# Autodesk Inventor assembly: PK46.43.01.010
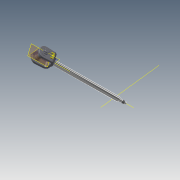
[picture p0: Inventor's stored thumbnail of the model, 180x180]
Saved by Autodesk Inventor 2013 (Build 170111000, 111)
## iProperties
Shininess: 64.0
Length Units: 11269
Angle Units: 11279
Time Units: 11290
Mass Units: 11283
Length Display Precision: 3
Angle Display Precision: 2
Compacted: True
Created: 2004-11
Part Number: PK46.43.01.010
Document SubType Name: Assembly
Designer: ELarisa
Manufacturer: Standard
Standards Organization: Custom
Mass: 71216.7 g
Surface Area: 7364.67 cm^2
Volume: 9076.79 cm^3
Density: 7.84603 g/cm^3
Density: 0.0
Volumn: 0.0
Area: 0.0
PropertySet Name: Model Information
Control State: 0
Master: False
Checked Out: False
Checked Out Date: 2008-10-09
Last Check In Date: 2008-10-09
Author: ELarisa
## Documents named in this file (8)
- D:\FrontLoaderVault\Data\Assy, Chassis, Front\PK46.43.01.010.iam
- D:\FrontLoaderVault\Data\Assy, Chassis, Front\PK46.43.01.001.ipt
- D:\FrontLoaderVault\Data\Assy, Chassis, Front\PK46.43.01.008.ipt
- D:\FrontLoaderVault\Data\Assy, Chassis, Front\PK30.25.00.005.ipt
- D:\FrontLoaderVault\Data\Assy, Chassis, Front\PK46.25.00.007.ipt
- D:\FrontLoaderVault\Data\Assy, Chassis, Front\PK46.25.00.010.iam
- D:\FrontLoaderVault\Data\Assy, Chassis, Front\PK46.25.00.005.ipt
- D:\FrontLoaderVault\Data\Assy, Chassis, Front\PK46.25.00.008.ipt
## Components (8 placed, 7 different names)
1. PK46.43.01.001:1 — Insert:1, Mate:5
2. PK46.43.01.008:1 — Angle:1, Mate:2, Insert:1, Mate:4, Mate:3, Mate:5
3. PK30.25.00.005:1 — Mate:2, Mate:4, Mate:3
4. PK46.25.00.007:1 — Insert:6
5. PK46.25.00.008:1 — Insert:6
6. PK46.25.00.005:1
7. PK46.25.00.010:2 [sub-assembly]
8. PK46.25.00.005:2
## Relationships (7: Mate 4, Insert 2, Angle 1)
- Angle:1: PK46.43.01.008:1
- Mate:2: PK46.43.01.008:1 ↔ PK30.25.00.005:1
- Insert:1: PK46.43.01.001:1 ↔ PK46.43.01.008:1
- Mate:4: PK46.43.01.008:1 ↔ PK30.25.00.005:1
- Mate:3: PK46.43.01.008:1 ↔ PK30.25.00.005:1
- Mate:5: PK46.43.01.001:1 ↔ PK46.43.01.008:1
- Insert:6: PK46.25.00.007:1 ↔ PK46.25.00.008:1
